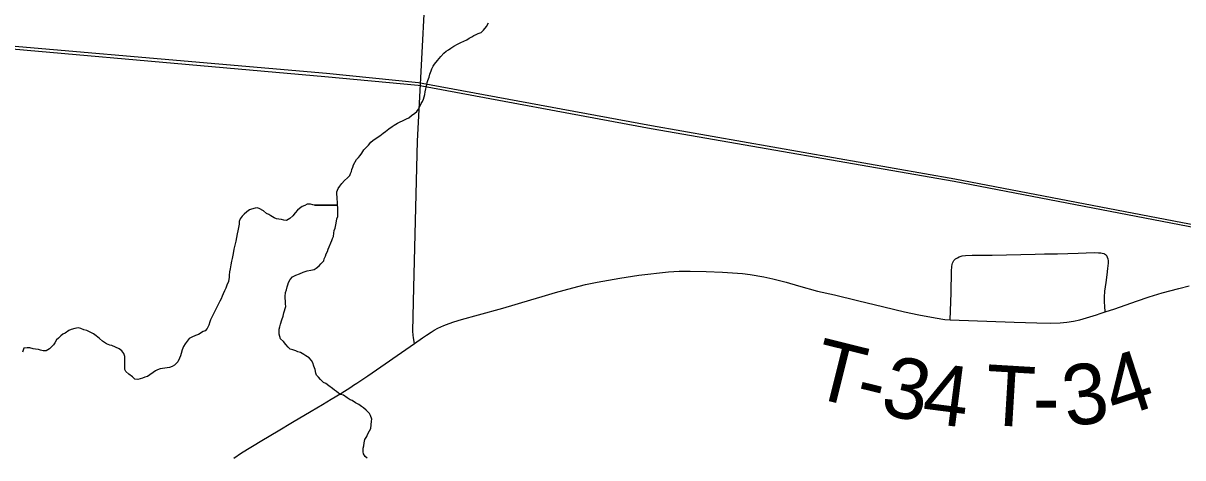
# Model space of a CAD drawing. Extents: x 2.1 to 73.9, y 4 to 26.
# Drawn here: x 44.457 to 45.001, y 22.787 to 22.991 of the extents above; entities that cross this region are included whole.
import ezdxf

# ---------------------------------------------------------------- set-up
doc = ezdxf.new("R2010")
doc.units = 0
for name, color, linetype in [('GM_X_Minor_River', 7, 'Continuous'), ('GM_X_Rail_Line', 7, 'Continuous'), ('GM_X_Township_Road', 7, 'Continuous'), ('GM_X_Township_Road_Text', 7, 'Continuous')]:
    doc.layers.add(name, color=color, linetype=linetype)

msp = doc.modelspace()

# ---------------------------------------------------------------- linework, layer by layer
at = {"layer": 'GM_X_Minor_River'}
for points in [[(44.58913, 22.87471), (44.59008, 22.87489), (44.5918, 22.87524), (44.59333, 22.8756), (44.59429, 22.87615), (44.59563, 22.87727), (44.59641, 22.87821), (44.59776, 22.87971), (44.59797, 22.88065), (44.59856, 22.88178), (44.59896, 22.88292), (44.59954, 22.88405), (44.59994, 22.88518), (44.60153, 22.88915), (44.60192, 22.89009), (44.60232, 22.89103), (44.60253, 22.89274), (44.60274, 22.89388), (44.60314, 22.89501), (44.60354, 22.89652), (44.60376, 22.89823), (44.60397, 22.89937), (44.60437, 22.9005), (44.60439, 22.90183), (44.60441, 22.90354), (44.60443, 22.90468), (44.60426, 22.90582), (44.60429, 22.90753), (44.60411, 22.90849), (44.60413, 22.90963), (44.60396, 22.91096), (44.60398, 22.9121), (44.60457, 22.91361), (44.60535, 22.91474), (44.60632, 22.91605), (44.60748, 22.91736), (44.60903, 22.91867), (44.61, 22.91979), (44.61039, 22.92074), (44.61079, 22.92168), (44.61099, 22.92263), (44.61139, 22.92376), (44.61178, 22.92471), (44.61316, 22.92734), (44.61412, 22.92828), (44.6149, 22.92922), (44.61568, 22.93034), (44.61665, 22.93185), (44.61781, 22.93316), (44.61878, 22.93409), (44.61994, 22.93541), (44.6209, 22.93615), (44.62244, 22.93727), (44.62417, 22.93838), (44.62571, 22.93968), (44.62687, 22.94043), (44.62841, 22.94173), (44.62995, 22.94285), (44.63091, 22.9434), (44.63244, 22.94433), (44.6334, 22.94488), (44.63513, 22.94561), (44.63666, 22.94635), (44.63781, 22.9469), (44.63897, 22.94802), (44.64051, 22.94914), (44.64147, 22.94988), (44.64225, 22.95101), (44.64303, 22.95252), (44.64362, 22.95365), (44.64421, 22.95459), (44.6446, 22.95572), (44.645, 22.95667), (44.64521, 22.9578), (44.64542, 22.95913), (44.64623, 22.96254), (44.64644, 22.96349), (44.64664, 22.96443), (44.64724, 22.96594), (44.64764, 22.96746), (44.64824, 22.96897), (44.64863, 22.96991), (44.64922, 22.97123), (44.64981, 22.97217), (44.65117, 22.97386), (44.65194, 22.9748), (44.65272, 22.97574), (44.65426, 22.97723), (44.65523, 22.97817), (44.65638, 22.97891), (44.65753, 22.97965), (44.65888, 22.98058), (44.6606, 22.9815), (44.66214, 22.98224), (44.66367, 22.98297), (44.66501, 22.98352), (44.66616, 22.98426), (44.66732, 22.985), (44.66828, 22.98556), (44.66943, 22.98611), (44.67038, 22.98648)], [(44.67038, 22.98648), (44.67172, 22.98702), (44.67288, 22.98815), (44.67424, 22.98983), (44.67522, 22.99153)], [(44.59342, 22.90581), (44.60426, 22.90582), (44.59266, 22.90601), (44.59152, 22.90622), (44.59, 22.90624), (44.58885, 22.90569), (44.5877, 22.90514), (44.58636, 22.90421), (44.5854, 22.90346), (44.58442, 22.90215), (44.58326, 22.90084), (44.58191, 22.89953), (44.58037, 22.8986), (44.57905, 22.89881), (44.57791, 22.89902), (44.57677, 22.89923), (44.57563, 22.89944), (44.5745, 22.89984), (44.57299, 22.90081), (44.57205, 22.90139), (44.57092, 22.90198), (44.56942, 22.90315), (44.56753, 22.90432), (44.56658, 22.90452), (44.56563, 22.90435), (44.56391, 22.904), (44.56296, 22.90363), (44.56161, 22.9027), (44.56045, 22.90158), (44.55949, 22.90064), (44.55851, 22.89933), (44.55812, 22.8982), (44.5581, 22.89687), (44.55769, 22.89535), (44.55748, 22.89384), (44.55707, 22.89232), (44.55686, 22.89062), (44.55645, 22.88891), (44.55604, 22.88702), (44.55563, 22.88513), (44.55522, 22.88304), (44.5548, 22.88077), (44.5544, 22.87945), (44.55418, 22.87774), (44.55377, 22.87585), (44.55356, 22.87452), (44.55335, 22.873), (44.55333, 22.87205), (44.55311, 22.86997), (44.55232, 22.86827), (44.55173, 22.86676), (44.55114, 22.86563), (44.55054, 22.86412), (44.55015, 22.86298), (44.54956, 22.86185), (44.54897, 22.86072), (44.54838, 22.8594), (44.54583, 22.8545), (44.54524, 22.85318), (44.54464, 22.85186), (44.54425, 22.85092), (44.54385, 22.8494), (44.54306, 22.84789), (44.54209, 22.84677), (44.54114, 22.84641), (44.53902, 22.84511), (44.53749, 22.84456), (44.53577, 22.84383), (44.53462, 22.84309), (44.53365, 22.84196), (44.53268, 22.84065), (44.5319, 22.83933), (44.5313, 22.83782), (44.53089, 22.83612), (44.5305, 22.83498), (44.5301, 22.83385), (44.52931, 22.83215), (44.52777, 22.83066), (44.52661, 22.82992), (44.52528, 22.82956), (44.52432, 22.82938), (44.52318, 22.82921), (44.52203, 22.82904), (44.52089, 22.82887), (44.51974, 22.8285), (44.51878, 22.82795), (44.51494, 22.82535), (44.51379, 22.82499), (44.51264, 22.82444), (44.5115, 22.82427), (44.51054, 22.8239), (44.50903, 22.82411), (44.5079, 22.82508), (44.50621, 22.82644), (44.5049, 22.8276), (44.50434, 22.82856), (44.50436, 22.82989), (44.50438, 22.83084), (44.5044, 22.83217), (44.50441, 22.83312), (44.50444, 22.83464)], [(44.61818, 22.78685), (44.61724, 22.78762), (44.6165, 22.78896), (44.61632, 22.78992), (44.61635, 22.79163), (44.61656, 22.79276), (44.61677, 22.79409), (44.61717, 22.79561), (44.61796, 22.79711), (44.61835, 22.79806), (44.61933, 22.79975), (44.61992, 22.80088), (44.62013, 22.80259), (44.62016, 22.8043), (44.62037, 22.80524), (44.61982, 22.80696), (44.61927, 22.80792), (44.61777, 22.80947), (44.61646, 22.81063), (44.61551, 22.81121), (44.6142, 22.81218), (44.61269, 22.81297), (44.61118, 22.81394), (44.61024, 22.81434), (44.60873, 22.81531), (44.60704, 22.81648), (44.60571, 22.81688), (44.60477, 22.81746), (44.60383, 22.81824), (44.60289, 22.81882), (44.60195, 22.8196), (44.60026, 22.82095), (44.59876, 22.82193), (44.59763, 22.82252), (44.59632, 22.82387), (44.59538, 22.82502), (44.59445, 22.82599), (44.59408, 22.82694), (44.59373, 22.82866), (44.59318, 22.83019), (44.59264, 22.83172), (44.59208, 22.83287), (44.59096, 22.83402), (44.58945, 22.835), (44.58851, 22.83558), (44.58682, 22.83656), (44.58568, 22.83696), (44.58474, 22.83735), (44.58322, 22.83776), (44.58209, 22.83815), (44.58115, 22.83912), (44.58003, 22.84028), (44.57891, 22.84181), (44.57741, 22.84298), (44.57724, 22.84412), (44.57687, 22.84527), (44.57689, 22.84641), (44.57691, 22.84755), (44.57712, 22.84868), (44.57751, 22.84982), (44.57812, 22.8519), (44.57872, 22.8536), (44.57912, 22.8553), (44.57993, 22.85814), (44.57976, 22.85947), (44.57978, 22.8608), (44.57961, 22.86194), (44.57962, 22.86289), (44.57984, 22.86479), (44.58024, 22.86611), (44.58064, 22.86744), (44.58085, 22.86838), (44.58125, 22.86952), (44.58203, 22.87084), (44.58319, 22.87215), (44.58473, 22.87288), (44.58645, 22.87362), (44.58817, 22.87435), (44.58913, 22.87471)], [(44.50444, 22.83464), (44.50389, 22.83617), (44.50296, 22.83732), (44.50164, 22.83829), (44.49994, 22.83908), (44.49824, 22.83987), (44.49729, 22.84007), (44.49578, 22.84067), (44.49484, 22.84125), (44.4939, 22.84184), (44.4924, 22.84319), (44.4909, 22.84435), (44.48958, 22.84532), (44.48656, 22.84689), (44.48505, 22.8473), (44.48372, 22.84789), (44.4824, 22.8481), (44.48087, 22.84793), (44.47915, 22.84739), (44.478, 22.84684), (44.47627, 22.84573), (44.47531, 22.84517), (44.47435, 22.84443), (44.47319, 22.84331), (44.47223, 22.84256), (44.47144, 22.84105), (44.47086, 22.84011), (44.46989, 22.83918), (44.46893, 22.83824), (44.46739, 22.83732), (44.46606, 22.83734), (44.46474, 22.83774), (44.46379, 22.83795), (44.46246, 22.83816), (44.46132, 22.83836), (44.45981, 22.83877), (44.45848, 22.83879), (44.45695, 22.83862), (44.45635, 22.83673)]]:
    msp.add_lwpolyline(points, dxfattribs=at)
at = {"layer": 'GM_X_Rail_Line'}
for points in [[(44.39292, 22.98448), (44.59837, 22.96628), (44.6422, 22.96221), (44.75155, 22.9419), (44.89395, 22.91704), (45.1259, 22.87248), (45.14755, 22.86877), (45.16796, 22.8663), (45.18714, 22.86382), (45.20508, 22.86135), (45.22116, 22.86135), (45.24652, 22.86258), (45.2725, 22.86506), (45.32446, 22.87558), (45.37394, 22.88672), (45.41353, 22.896), (45.4494, 22.9028), (45.48219, 22.90528), (45.51188, 22.90713), (45.54219, 22.90652), (45.58425, 22.9028)], [(44.39302, 22.98572), (44.59909, 22.96782), (44.64238, 22.96344), (44.75179, 22.94321), (44.89418, 22.91826), (45.12613, 22.87371), (45.14773, 22.87), (45.16812, 22.86753), (45.1873, 22.86505), (45.20516, 22.86259), (45.22113, 22.86259), (45.24643, 22.86382), (45.27232, 22.86629), (45.3242, 22.87679), (45.37366, 22.88793), (45.41327, 22.89721), (45.44924, 22.90404), (45.4821, 22.90652), (45.51185, 22.90838), (45.54225, 22.90776), (45.58442, 22.90404)]]:
    msp.add_lwpolyline(points, dxfattribs=at)
at = {"layer": 'GM_X_Township_Road'}
for points in [[(44.6404, 22.84086), (44.63994, 22.8435), (44.63974, 22.84476), (44.63963, 22.84667), (44.64006, 22.86712), (44.64191, 22.93595), (44.64734, 23.04042), (44.64838, 23.06432), (44.64913, 23.08731), (44.64966, 23.10563), (44.65077, 23.14602), (44.65186, 23.19107), (44.656, 23.34725)], [(44.8946, 22.88066), (44.89543, 22.88111), (44.89634, 22.88153), (44.89722, 22.88185), (44.89774, 22.882), (44.89928, 22.88224), (44.90238, 22.88239), (44.91172, 22.88236), (44.93195, 22.88282), (44.93631, 22.88293), (44.94253, 22.88295), (44.95217, 22.88326), (44.95964, 22.88351), (44.96175, 22.88346), (44.96274, 22.88344), (44.96347, 22.88333), (44.96417, 22.88315), (44.96461, 22.88292), (44.965, 22.88264)], [(44.8921, 22.85187), (44.89254, 22.86462), (44.89262, 22.87485), (44.89278, 22.87704), (44.89291, 22.87788), (44.89308, 22.87862), (44.89338, 22.87921), (44.89381, 22.87983), (44.89417, 22.88023), (44.8946, 22.88066)], [(44.96482, 22.85562), (44.96466, 22.85833), (44.96454, 22.86018), (44.96453, 22.86265), (44.96475, 22.86542), (44.96525, 22.86941), (44.96575, 22.87308), (44.96616, 22.87613), (44.96641, 22.87857), (44.96637, 22.87979), (44.96627, 22.88039), (44.96598, 22.88126), (44.96579, 22.88164), (44.96556, 22.88197), (44.96531, 22.88229), (44.965, 22.88264)], [(44.6404, 22.84086), (44.64421, 22.84344), (44.64605, 22.84476), (44.64825, 22.84619), (44.64974, 22.8471), (44.65144, 22.84795), (44.6528, 22.84862), (44.65419, 22.84922), (44.65542, 22.84975), (44.65678, 22.85028), (44.65896, 22.85098), (44.66247, 22.85204), (44.67056, 22.85428), (44.68194, 22.85748), (44.69506, 22.86137), (44.70042, 22.86296), (44.7067, 22.86476), (44.71478, 22.86698), (44.72079, 22.86853), (44.72624, 22.86971), (44.73695, 22.87156), (44.74587, 22.87285), (44.75975, 22.87446), (44.76469, 22.87479), (44.76995, 22.87485), (44.7774, 22.8747), (44.78516, 22.87432), (44.79444, 22.87371), (44.79813, 22.8733), (44.80453, 22.87217), (44.80876, 22.87121), (44.81506, 22.86957), (44.82073, 22.86792), (44.82975, 22.86547), (44.83763, 22.86361), (44.84851, 22.86098), (44.86091, 22.85801), (44.87061, 22.85574), (44.87731, 22.85433), (44.88496, 22.85285), (44.88959, 22.85215), (44.8921, 22.85187)], [(44.96482, 22.85562), (44.96932, 22.85704), (44.97957, 22.86072), (44.98546, 22.86269), (44.99169, 22.86458), (44.99947, 22.86669), (45.00428, 22.86791)], [(44.8921, 22.85187), (44.92217, 22.85089), (44.93274, 22.85052), (44.93929, 22.85039), (44.94366, 22.85049), (44.94679, 22.85076), (44.9499, 22.85126), (44.95295, 22.85199), (44.96071, 22.85433), (44.96249, 22.85488), (44.96482, 22.85562)], [(44.55557, 22.78699), (44.55918, 22.78935), (44.56874, 22.79515), (44.57646, 22.79981), (44.58312, 22.80378), (44.59191, 22.80902), (44.59725, 22.81218), (44.60125, 22.81457), (44.60577, 22.8173), (44.61048, 22.82033), (44.61177, 22.82119), (44.61333, 22.82219), (44.61855, 22.82556), (44.6404, 22.84086)]]:
    msp.add_lwpolyline(points, dxfattribs=at)

# ---------------------------------------------------------------- texts
at = {"layer": 'GM_X_Township_Road_Text'}
for s, rotation, p in [('T', 345.9929, (44.8255, 22.81609)), ('3', 347.9887, (44.85851, 22.80794)), ('4', 18.0718, (44.96952, 22.80521)), ('4', 352.6887, (44.87813, 22.80387)), ('T', 356.5609, (44.90784, 22.80268)), ('3', 7.8794, (44.94683, 22.80158)), ('-', 346.3005, (44.84628, 22.8109)), ('-', 359.6822, (44.93074, 22.80135))]:
    msp.add_text(s, height=0.02841, rotation=rotation, dxfattribs=at).set_placement(p)

doc.saveas('drawing.dxf')
